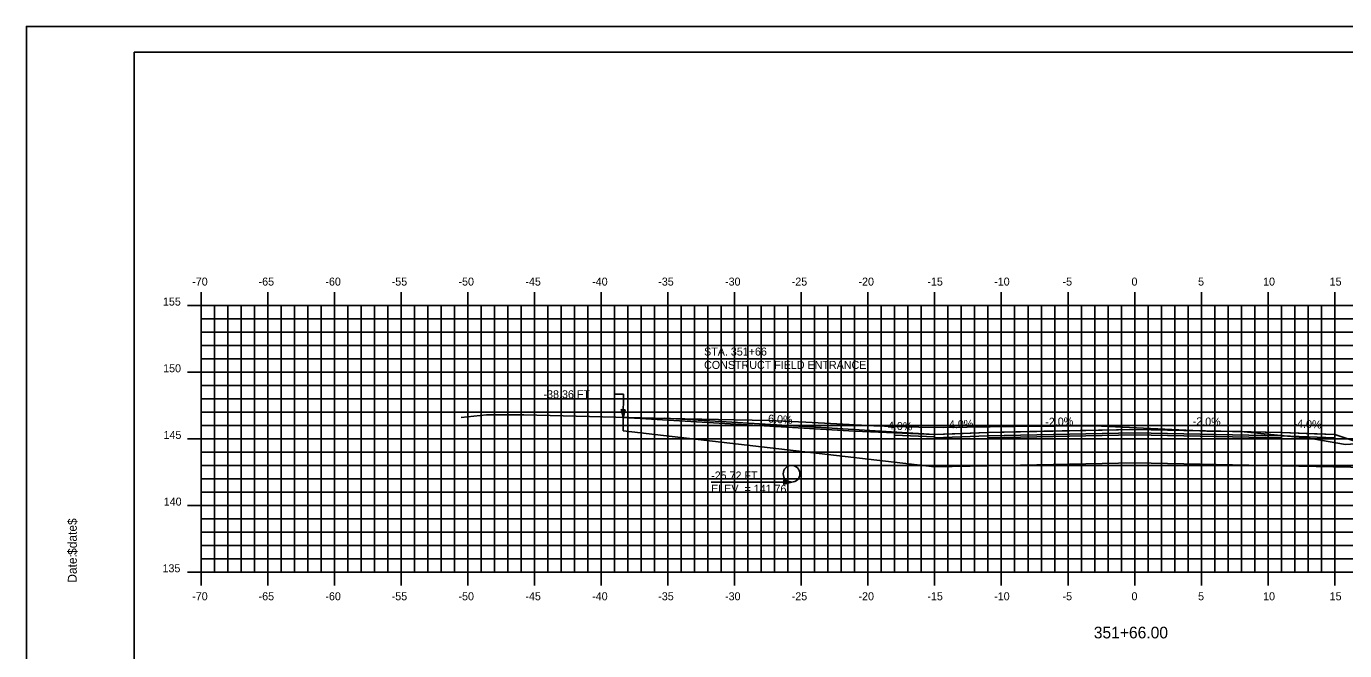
# Model space of a CAD drawing. Extents: x 1144751 to 1144921, y 608981 to 609091.
# Drawn here: x 1144750.5 to 1144849.4, y 609044.5 to 609091.3 of the extents above; entities that cross this region are included whole.
import ezdxf

# ---------------------------------------------------------------- set-up
doc = ezdxf.new("R2010")
doc.units = 0
for name, color, linetype in [('ANNOTATION', 7, 'Continuous'), ('BORDER', 7, 'Continuous'), ('D_Drainage_Culvert', 7, 'Continuous'), ('D_Roadway_Centerline', 7, 'Continuous'), ('D_Roadway_Edge_Shoulder', 7, 'Continuous'), ('D_Roadway_Edge_TW', 7, 'Continuous'), ('D_Roadway_Pavement', 7, 'Continuous'), ('D_Roadway_SubGrade', 7, 'Continuous'), ('D_Text_Standard', 7, 'Continuous'), ('H_V ANNOTATION', 7, 'Continuous'), ('MAJOR', 7, 'Continuous'), ('MINOR', 7, 'Continuous'), ('PLOT BOUNDARY', 7, 'Continuous'), ('S_Roadway_Centerline', 7, 'Continuous')]:
    doc.layers.add(name, color=color, linetype=linetype)

msp = doc.modelspace()

# ---------------------------------------------------------------- linework, layer by layer
msp.add_lwpolyline([(1144798.38, 609061.883), (1144810.934, 609061.13), (1144818.619, 609060.668), (1144820.138, 609060.729), (1144822.619, 609060.828), (1144826.796, 609060.912), (1144833.619, 609061.048), (1144837.796, 609060.965), (1144844.619, 609060.828), (1144847.1, 609060.729), (1144848.619, 609060.668), (1144853.41, 609059.072)])
at = {"layer": 'BORDER'}
msp.add_lwpolyline([(1144758.619, 608984.335), (1144918.619, 608984.335), (1144918.619, 609089.335), (1144758.619, 609089.335)], close=True, dxfattribs=at)
at = {"layer": 'D_Drainage_Culvert'}
msp.add_circle((1144807.894, 609057.719), 0.625, dxfattribs=at)
at = {"layer": 'D_Roadway_Edge_Shoulder'}
for points in [[(1144818.619, 609060.668), (1144815.619, 609060.788), (1144815.612, 609060.622), (1144818.617, 609060.502)], [(1144822.619, 609060.828), (1144818.619, 609060.668), (1144818.619, 609060.418), (1144822.619, 609060.578)], [(1144844.619, 609060.828), (1144848.619, 609060.668), (1144848.619, 609060.418), (1144844.619, 609060.578)]]:
    msp.add_lwpolyline(points, close=True, dxfattribs=at)
at = {"layer": 'D_Roadway_Edge_TW'}
msp.add_lwpolyline([(1144822.619, 609060.578), (1144822.619, 609060.828), (1144833.619, 609061.048), (1144844.619, 609060.828), (1144844.619, 609060.578), (1144833.619, 609060.798)], close=True, dxfattribs=at)
at = {"layer": 'D_Roadway_Pavement'}
msp.add_lwpolyline([(1144822.619, 609060.412), (1144822.619, 609060.578), (1144833.619, 609060.798), (1144844.619, 609060.578), (1144844.619, 609060.412), (1144833.619, 609060.632)], close=True, dxfattribs=at)
at = {"layer": 'D_Roadway_SubGrade'}
for p, q in [((1144812.619, 609060.908), (1144795.26, 609061.95)), ((1144818.619, 609060.668), (1144812.619, 609060.908))]:
    msp.add_line(p, q, dxfattribs=at)
for points in [[(1144795.26, 609060.95), (1144818.619, 609058.248), (1144822.619, 609058.328), (1144822.619, 609060.412), (1144822.619, 609060.578), (1144818.619, 609060.418), (1144818.619, 609060.668), (1144812.619, 609060.908), (1144795.26, 609061.95)], [(1144822.619, 609058.328), (1144822.619, 609060.412), (1144833.619, 609060.632), (1144844.619, 609060.412), (1144844.619, 609058.328), (1144833.619, 609058.548)], [(1144844.619, 609060.412), (1144844.619, 609060.578), (1144848.619, 609060.418), (1144848.619, 609060.668), (1144848.619, 609060.668), (1144856.342, 609058.094), (1144844.619, 609058.328)]]:
    msp.add_lwpolyline(points, close=True, dxfattribs=at)
at = {"layer": 'D_Text_Standard'}
msp.add_line((1144801.864, 609057.094), (1144806.622, 609057.094), dxfattribs=at)
for points in [[(1144795.26, 609061.95), (1144795.293, 609063.685), (1144794.613, 609063.685)], [(1144807.894, 609057.094), (1144807.302, 609057.094), (1144806.622, 609057.094)]]:
    msp.add_lwpolyline(points, dxfattribs=at)
for points in [[(1144795.26, 609061.95), (1144795.125, 609062.535), (1144795.416, 609062.529)], [(1144807.894, 609057.094), (1144807.312, 609056.948), (1144807.312, 609057.239)]]:
    msp.add_lwpolyline(points, close=True, dxfattribs=at)
at = {"layer": 'MAJOR'}
for p, q in [((1144763.619, 609071.337), (1144763.619, 609070.335)), ((1144768.619, 609071.337), (1144768.619, 609070.335)), ((1144773.619, 609071.337), (1144773.619, 609070.335)), ((1144778.619, 609071.337), (1144778.619, 609070.335)), ((1144783.619, 609071.337), (1144783.619, 609070.335)), ((1144788.619, 609071.337), (1144788.619, 609070.335)), ((1144793.619, 609071.337), (1144793.619, 609070.335)), ((1144798.619, 609071.337), (1144798.619, 609070.335)), ((1144803.619, 609071.337), (1144803.619, 609070.335)), ((1144808.619, 609071.337), (1144808.619, 609070.335)), ((1144813.619, 609071.337), (1144813.619, 609070.335)), ((1144818.619, 609071.337), (1144818.619, 609070.335)), ((1144823.619, 609071.337), (1144823.619, 609070.335)), ((1144828.619, 609071.337), (1144828.619, 609070.335)), ((1144833.619, 609071.337), (1144833.619, 609070.335)), ((1144838.619, 609071.337), (1144838.619, 609070.335)), ((1144843.619, 609071.337), (1144843.619, 609070.335)), ((1144848.619, 609071.337), (1144848.619, 609070.335)), ((1144762.617, 609070.335), (1144763.619, 609070.335)), ((1144763.619, 609070.335), (1144903.619, 609070.335)), ((1144763.619, 609050.335), (1144763.619, 609070.335)), ((1144763.619, 609050.335), (1144763.619, 609070.335)), ((1144763.619, 609070.335), (1144903.619, 609070.335)), ((1144768.619, 609050.335), (1144768.619, 609070.335)), ((1144773.619, 609050.335), (1144773.619, 609070.335)), ((1144778.619, 609050.335), (1144778.619, 609070.335)), ((1144783.619, 609050.335), (1144783.619, 609070.335)), ((1144788.619, 609050.335), (1144788.619, 609070.335)), ((1144793.619, 609050.335), (1144793.619, 609070.335)), ((1144798.619, 609050.335), (1144798.619, 609070.335)), ((1144803.619, 609050.335), (1144803.619, 609070.335)), ((1144808.619, 609050.335), (1144808.619, 609070.335)), ((1144813.619, 609050.335), (1144813.619, 609070.335)), ((1144818.619, 609050.335), (1144818.619, 609070.335)), ((1144823.619, 609050.335), (1144823.619, 609070.335)), ((1144828.619, 609050.335), (1144828.619, 609070.335)), ((1144833.619, 609050.335), (1144833.619, 609070.335)), ((1144838.619, 609050.335), (1144838.619, 609070.335)), ((1144843.619, 609050.335), (1144843.619, 609070.335)), ((1144848.619, 609050.335), (1144848.619, 609070.335)), ((1144762.617, 609065.335), (1144763.619, 609065.335)), ((1144763.619, 609065.335), (1144903.619, 609065.335)), ((1144762.617, 609060.335), (1144763.619, 609060.335)), ((1144763.619, 609060.335), (1144903.619, 609060.335)), ((1144762.617, 609055.335), (1144763.619, 609055.335)), ((1144763.619, 609055.335), (1144903.619, 609055.335)), ((1144762.617, 609050.335), (1144763.619, 609050.335)), ((1144763.619, 609050.335), (1144903.619, 609050.335)), ((1144763.619, 609050.335), (1144903.619, 609050.335)), ((1144763.619, 609049.333), (1144763.619, 609050.335)), ((1144768.619, 609049.333), (1144768.619, 609050.335)), ((1144773.619, 609049.333), (1144773.619, 609050.335)), ((1144778.619, 609049.333), (1144778.619, 609050.335)), ((1144783.619, 609049.333), (1144783.619, 609050.335)), ((1144788.619, 609049.333), (1144788.619, 609050.335)), ((1144793.619, 609049.333), (1144793.619, 609050.335)), ((1144798.619, 609049.333), (1144798.619, 609050.335)), ((1144803.619, 609049.333), (1144803.619, 609050.335)), ((1144808.619, 609049.333), (1144808.619, 609050.335)), ((1144813.619, 609049.333), (1144813.619, 609050.335)), ((1144818.619, 609049.333), (1144818.619, 609050.335)), ((1144823.619, 609049.333), (1144823.619, 609050.335)), ((1144828.619, 609049.333), (1144828.619, 609050.335)), ((1144833.619, 609049.333), (1144833.619, 609050.335)), ((1144838.619, 609049.333), (1144838.619, 609050.335)), ((1144843.619, 609049.333), (1144843.619, 609050.335)), ((1144848.619, 609049.333), (1144848.619, 609050.335))]:
    msp.add_line(p, q, dxfattribs=at)
at = {"layer": 'MINOR'}
for p, q in [((1144764.619, 609050.335), (1144764.619, 609070.335)), ((1144765.619, 609050.335), (1144765.619, 609070.335)), ((1144766.619, 609050.335), (1144766.619, 609070.335)), ((1144767.619, 609050.335), (1144767.619, 609070.335)), ((1144769.619, 609050.335), (1144769.619, 609070.335)), ((1144770.619, 609050.335), (1144770.619, 609070.335)), ((1144771.619, 609050.335), (1144771.619, 609070.335)), ((1144772.619, 609050.335), (1144772.619, 609070.335)), ((1144774.619, 609050.335), (1144774.619, 609070.335)), ((1144775.619, 609050.335), (1144775.619, 609070.335)), ((1144776.619, 609050.335), (1144776.619, 609070.335)), ((1144777.619, 609050.335), (1144777.619, 609070.335)), ((1144779.619, 609050.335), (1144779.619, 609070.335)), ((1144780.619, 609050.335), (1144780.619, 609070.335)), ((1144781.619, 609050.335), (1144781.619, 609070.335)), ((1144782.619, 609050.335), (1144782.619, 609070.335)), ((1144784.619, 609050.335), (1144784.619, 609070.335)), ((1144785.619, 609050.335), (1144785.619, 609070.335)), ((1144786.619, 609050.335), (1144786.619, 609070.335)), ((1144787.619, 609050.335), (1144787.619, 609070.335)), ((1144789.619, 609050.335), (1144789.619, 609070.335)), ((1144790.619, 609050.335), (1144790.619, 609070.335)), ((1144791.619, 609050.335), (1144791.619, 609070.335)), ((1144792.619, 609050.335), (1144792.619, 609070.335)), ((1144794.619, 609050.335), (1144794.619, 609070.335)), ((1144795.619, 609050.335), (1144795.619, 609070.335)), ((1144796.619, 609050.335), (1144796.619, 609070.335)), ((1144797.619, 609050.335), (1144797.619, 609070.335)), ((1144799.619, 609050.335), (1144799.619, 609070.335)), ((1144800.619, 609050.335), (1144800.619, 609070.335)), ((1144801.619, 609050.335), (1144801.619, 609070.335)), ((1144802.619, 609050.335), (1144802.619, 609070.335)), ((1144804.619, 609050.335), (1144804.619, 609070.335)), ((1144805.619, 609050.335), (1144805.619, 609070.335)), ((1144806.619, 609050.335), (1144806.619, 609070.335)), ((1144807.619, 609050.335), (1144807.619, 609070.335)), ((1144809.619, 609050.335), (1144809.619, 609070.335)), ((1144810.619, 609050.335), (1144810.619, 609070.335)), ((1144811.619, 609050.335), (1144811.619, 609070.335)), ((1144812.619, 609050.335), (1144812.619, 609070.335)), ((1144814.619, 609050.335), (1144814.619, 609070.335)), ((1144815.619, 609050.335), (1144815.619, 609070.335)), ((1144816.619, 609050.335), (1144816.619, 609070.335)), ((1144817.619, 609050.335), (1144817.619, 609070.335)), ((1144819.619, 609050.335), (1144819.619, 609070.335)), ((1144820.619, 609050.335), (1144820.619, 609070.335)), ((1144821.619, 609050.335), (1144821.619, 609070.335)), ((1144822.619, 609050.335), (1144822.619, 609070.335)), ((1144824.619, 609050.335), (1144824.619, 609070.335)), ((1144825.619, 609050.335), (1144825.619, 609070.335)), ((1144826.619, 609050.335), (1144826.619, 609070.335)), ((1144827.619, 609050.335), (1144827.619, 609070.335)), ((1144829.619, 609050.335), (1144829.619, 609070.335)), ((1144830.619, 609050.335), (1144830.619, 609070.335)), ((1144831.619, 609050.335), (1144831.619, 609070.335)), ((1144832.619, 609050.335), (1144832.619, 609070.335)), ((1144834.619, 609050.335), (1144834.619, 609070.335)), ((1144835.619, 609050.335), (1144835.619, 609070.335)), ((1144836.619, 609050.335), (1144836.619, 609070.335)), ((1144837.619, 609050.335), (1144837.619, 609070.335)), ((1144839.619, 609050.335), (1144839.619, 609070.335)), ((1144840.619, 609050.335), (1144840.619, 609070.335)), ((1144841.619, 609050.335), (1144841.619, 609070.335)), ((1144842.619, 609050.335), (1144842.619, 609070.335)), ((1144844.619, 609050.335), (1144844.619, 609070.335)), ((1144845.619, 609050.335), (1144845.619, 609070.335)), ((1144846.619, 609050.335), (1144846.619, 609070.335)), ((1144847.619, 609050.335), (1144847.619, 609070.335)), ((1144763.619, 609069.335), (1144903.619, 609069.335)), ((1144763.619, 609069.335), (1144764.621, 609069.335)), ((1144763.619, 609068.335), (1144903.619, 609068.335)), ((1144763.619, 609068.335), (1144764.621, 609068.335)), ((1144763.619, 609067.335), (1144903.619, 609067.335)), ((1144763.619, 609067.335), (1144764.621, 609067.335)), ((1144763.619, 609066.335), (1144903.619, 609066.335)), ((1144763.619, 609066.335), (1144764.621, 609066.335)), ((1144763.619, 609064.335), (1144903.619, 609064.335)), ((1144763.619, 609064.335), (1144764.621, 609064.335)), ((1144763.619, 609063.335), (1144903.619, 609063.335)), ((1144763.619, 609063.335), (1144764.621, 609063.335)), ((1144763.619, 609062.335), (1144903.619, 609062.335)), ((1144763.619, 609062.335), (1144764.621, 609062.335)), ((1144763.619, 609061.335), (1144903.619, 609061.335)), ((1144763.619, 609061.335), (1144764.621, 609061.335)), ((1144763.619, 609059.335), (1144903.619, 609059.335)), ((1144763.619, 609059.335), (1144764.621, 609059.335)), ((1144763.619, 609058.335), (1144903.619, 609058.335)), ((1144763.619, 609058.335), (1144764.621, 609058.335)), ((1144763.619, 609057.335), (1144903.619, 609057.335)), ((1144763.619, 609057.335), (1144764.621, 609057.335)), ((1144763.619, 609056.335), (1144903.619, 609056.335)), ((1144763.619, 609056.335), (1144764.621, 609056.335)), ((1144763.619, 609054.335), (1144903.619, 609054.335)), ((1144763.619, 609054.335), (1144764.621, 609054.335)), ((1144763.619, 609053.335), (1144903.619, 609053.335)), ((1144763.619, 609053.335), (1144764.621, 609053.335)), ((1144763.619, 609052.335), (1144903.619, 609052.335)), ((1144763.619, 609052.335), (1144764.621, 609052.335)), ((1144763.619, 609051.335), (1144903.619, 609051.335)), ((1144763.619, 609051.335), (1144764.621, 609051.335))]:
    msp.add_line(p, q, dxfattribs=at)
at = {"layer": 'PLOT BOUNDARY'}
msp.add_lwpolyline([(1144750.526, 608981.276), (1144920.526, 608981.276), (1144920.526, 609091.276), (1144750.526, 609091.276)], close=True, dxfattribs=at)
at = {"layer": 'S_Roadway_Centerline'}
msp.add_lwpolyline([(1144783.122, 609061.95), (1144785.027, 609062.135), (1144787.81, 609062.15), (1144798.649, 609061.859), (1144806.19, 609061.719), (1144808.961, 609061.597), (1144814.062, 609061.329), (1144816.431, 609061.236), (1144817.427, 609061.225), (1144819.306, 609061.183), (1144824.536, 609061.274), (1144830.598, 609061.308), (1144839.021, 609060.925), (1144841.575, 609060.88), (1144845.067, 609060.537), (1144845.959, 609060.474), (1144846.963, 609060.332), (1144849.419, 609059.928), (1144851.267, 609060.05), (1144854.348, 609060.443), (1144871.318, 609059.866), (1144877.714, 609059.639)], dxfattribs=at)

# ---------------------------------------------------------------- texts
at = {"layer": 'ANNOTATION'}
for s, p in [('STA. 351+66', (1144801.335, 609066.587)), ('CONSTRUCT FIELD ENTRANCE', (1144801.335, 609065.585))]:
    msp.add_text(s, height=0.6, dxfattribs=at).set_placement(p)
for s, rotation, p in [('6.0%', 356.56637, (1144806.118, 609061.567)), ('4.0%', 357.70939, (1144815.108, 609061.042)), ('-4.0%', 2.29061, (1144819.435, 609061.102)), ('-2.0%', 1.14576, (1144826.922, 609061.315)), ('-2.0%', 358.85424, (1144837.962, 609061.362)), ('-4.0%', 357.70939, (1144845.515, 609061.193))]:
    msp.add_text(s, height=0.6, rotation=rotation, dxfattribs=at).set_placement(p)
at = {"layer": 'BORDER'}
for s, p in [('$date$', (1144754.304, 609051.64)), ('Date:', (1144754.304, 609049.552))]:
    msp.add_text(s, height=0.6696, rotation=90, dxfattribs=at).set_placement(p)
at = {"layer": 'D_Roadway_Centerline'}
for s, p in [('C', (1144833.614, 609061.048)), ('L', (1144833.619, 609061.041))]:
    msp.add_text(s, height=0.0146, dxfattribs=at).set_placement(p)
at = {"layer": 'D_Text_Standard'}
for s, p in [('-38.36 FT', (1144789.298, 609063.385)), ('-25.72 FT.', (1144801.864, 609057.294)), ('ELEV. = 141.76', (1144801.864, 609056.294))]:
    msp.add_text(s, height=0.6, dxfattribs=at).set_placement(p)
at = {"layer": 'H_V ANNOTATION'}
for s, height, p in [('-70', 0.6, (1144762.96, 609071.835)), ('-65', 0.6, (1144767.937, 609071.835)), ('-60', 0.6, (1144772.945, 609071.835)), ('-55', 0.6, (1144777.915, 609071.835)), ('-50', 0.6, (1144782.923, 609071.835)), ('-45', 0.6, (1144787.937, 609071.835)), ('-40', 0.6, (1144792.945, 609071.835)), ('-35', 0.6, (1144797.899, 609071.835)), ('-30', 0.6, (1144802.907, 609071.835)), ('-25', 0.6, (1144807.904, 609071.835)), ('-20', 0.6, (1144812.912, 609071.835)), ('-15', 0.6, (1144818.076, 609071.835)), ('-10', 0.6, (1144823.084, 609071.835)), ('-5', 0.6, (1144828.209, 609071.835)), ('0', 0.6, (1144833.378, 609071.835)), ('5', 0.6, (1144838.37, 609071.835)), ('10', 0.6, (1144843.244, 609071.835)), ('15', 0.6, (1144848.236, 609071.835)), ('155', 0.6, (1144760.765, 609070.335)), ('150', 0.6, (1144760.781, 609065.335)), ('145', 0.6, (1144760.808, 609060.335)), ('140', 0.6, (1144760.824, 609055.335)), ('135', 0.6, (1144760.733, 609050.335)), ('-70', 0.6, (1144762.96, 609048.235)), ('-65', 0.6, (1144767.937, 609048.235)), ('-60', 0.6, (1144772.945, 609048.235)), ('-55', 0.6, (1144777.915, 609048.235)), ('-50', 0.6, (1144782.923, 609048.235)), ('-45', 0.6, (1144787.937, 609048.235)), ('-40', 0.6, (1144792.945, 609048.235)), ('-35', 0.6, (1144797.899, 609048.235)), ('-30', 0.6, (1144802.907, 609048.235)), ('-25', 0.6, (1144807.904, 609048.235)), ('-20', 0.6, (1144812.912, 609048.235)), ('-15', 0.6, (1144818.076, 609048.235)), ('-10', 0.6, (1144823.084, 609048.235)), ('-5', 0.6, (1144828.209, 609048.235)), ('0', 0.6, (1144833.378, 609048.235)), ('5', 0.6, (1144838.37, 609048.235)), ('10', 0.6, (1144843.244, 609048.235)), ('15', 0.6, (1144848.236, 609048.235)), ('351+66.00', 0.875, (1144830.552, 609045.378))]:
    msp.add_text(s, height=height, dxfattribs=at).set_placement(p)
at = {"layer": 'MAJOR'}
msp.add_text('-', height=0.006, dxfattribs=at).set_placement((1144763.614, 609050.335))
at = {"layer": 'S_Roadway_Centerline'}
for s, p in [('L', (1144830.59, 609061.301)), ('C', (1144830.593, 609061.308))]:
    msp.add_text(s, height=0.0146, dxfattribs=at).set_placement(p)

doc.saveas('drawing.dxf')
